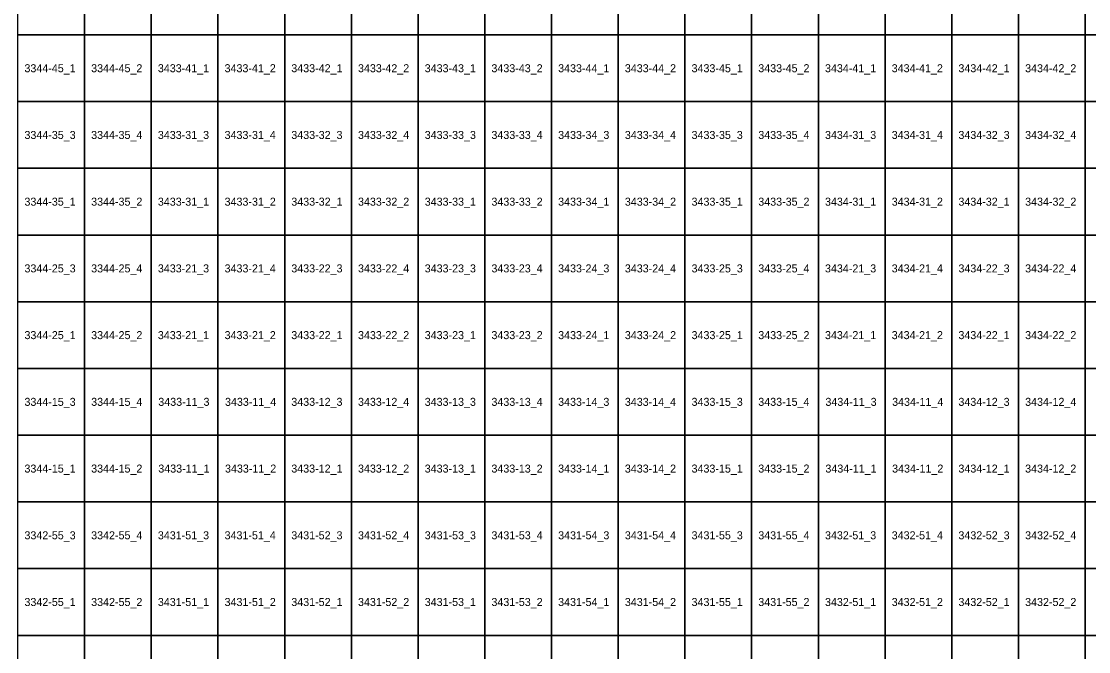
# Model space of a CAD drawing. Extents: x 312500 to 765000, y 172500 to 440000.
# Drawn here: x 595132 to 635129, y 269390 to 293007 of the extents above; entities that cross this region are included whole.
import ezdxf

# ---------------------------------------------------------------- set-up
doc = ezdxf.new("R2010")
doc.units = 0
doc.layers.add('Topo5_ramis_TKS2025', color=7, linetype='Continuous')
doc.layers.add('Topo5_ramis_TKS2025_Nr', color=7, linetype='Continuous')

msp = doc.modelspace()

# ---------------------------------------------------------------- linework, layer by layer
at = {"layer": 'Topo5_ramis_TKS2025'}
for points in [[(595000, 292500), (595000, 295000), (597500, 295000), (597500, 292500), (595000, 292500)], [(597500, 292500), (597500, 295000), (600000, 295000), (600000, 292500), (597500, 292500)], [(600000, 292500), (600000, 295000), (602500, 295000), (602500, 292500), (600000, 292500)], [(602500, 292500), (602500, 295000), (605000, 295000), (605000, 292500), (602500, 292500)], [(605000, 292500), (605000, 295000), (607500, 295000), (607500, 292500), (605000, 292500)], [(607500, 292500), (607500, 295000), (610000, 295000), (610000, 292500), (607500, 292500)], [(610000, 292500), (610000, 295000), (612500, 295000), (612500, 292500), (610000, 292500)], [(612500, 292500), (612500, 295000), (615000, 295000), (615000, 292500), (612500, 292500)], [(615000, 292500), (615000, 295000), (617500, 295000), (617500, 292500), (615000, 292500)], [(617500, 292500), (617500, 295000), (620000, 295000), (620000, 292500), (617500, 292500)], [(620000, 292500), (620000, 295000), (622500, 295000), (622500, 292500), (620000, 292500)], [(622500, 292500), (622500, 295000), (625000, 295000), (625000, 292500), (622500, 292500)], [(625000, 292500), (625000, 295000), (627500, 295000), (627500, 292500), (625000, 292500)], [(627500, 292500), (627500, 295000), (630000, 295000), (630000, 292500), (627500, 292500)], [(630000, 292500), (630000, 295000), (632500, 295000), (632500, 292500), (630000, 292500)], [(632500, 292500), (632500, 295000), (635000, 295000), (635000, 292500), (632500, 292500)], [(635000, 292500), (635000, 295000), (637500, 295000), (637500, 292500), (635000, 292500)], [(595000, 290000), (595000, 292500), (597500, 292500), (597500, 290000), (595000, 290000)], [(597500, 290000), (597500, 292500), (600000, 292500), (600000, 290000), (597500, 290000)], [(600000, 290000), (600000, 292500), (602500, 292500), (602500, 290000), (600000, 290000)], [(602500, 290000), (602500, 292500), (605000, 292500), (605000, 290000), (602500, 290000)], [(605000, 290000), (605000, 292500), (607500, 292500), (607500, 290000), (605000, 290000)], [(607500, 290000), (607500, 292500), (610000, 292500), (610000, 290000), (607500, 290000)], [(610000, 290000), (610000, 292500), (612500, 292500), (612500, 290000), (610000, 290000)], [(612500, 290000), (612500, 292500), (615000, 292500), (615000, 290000), (612500, 290000)], [(615000, 290000), (615000, 292500), (617500, 292500), (617500, 290000), (615000, 290000)], [(617500, 290000), (617500, 292500), (620000, 292500), (620000, 290000), (617500, 290000)], [(620000, 290000), (620000, 292500), (622500, 292500), (622500, 290000), (620000, 290000)], [(622500, 290000), (622500, 292500), (625000, 292500), (625000, 290000), (622500, 290000)], [(625000, 290000), (625000, 292500), (627500, 292500), (627500, 290000), (625000, 290000)], [(627500, 290000), (627500, 292500), (630000, 292500), (630000, 290000), (627500, 290000)], [(630000, 290000), (630000, 292500), (632500, 292500), (632500, 290000), (630000, 290000)], [(632500, 290000), (632500, 292500), (635000, 292500), (635000, 290000), (632500, 290000)], [(635000, 290000), (635000, 292500), (637500, 292500), (637500, 290000), (635000, 290000)], [(595000, 287500), (595000, 290000), (597500, 290000), (597500, 287500), (595000, 287500)], [(597500, 287500), (597500, 290000), (600000, 290000), (600000, 287500), (597500, 287500)], [(600000, 287500), (600000, 290000), (602500, 290000), (602500, 287500), (600000, 287500)], [(602500, 287500), (602500, 290000), (605000, 290000), (605000, 287500), (602500, 287500)], [(605000, 287500), (605000, 290000), (607500, 290000), (607500, 287500), (605000, 287500)], [(607500, 287500), (607500, 290000), (610000, 290000), (610000, 287500), (607500, 287500)], [(610000, 287500), (610000, 290000), (612500, 290000), (612500, 287500), (610000, 287500)], [(612500, 287500), (612500, 290000), (615000, 290000), (615000, 287500), (612500, 287500)], [(615000, 287500), (615000, 290000), (617500, 290000), (617500, 287500), (615000, 287500)], [(617500, 287500), (617500, 290000), (620000, 290000), (620000, 287500), (617500, 287500)], [(620000, 287500), (620000, 290000), (622500, 290000), (622500, 287500), (620000, 287500)], [(622500, 287500), (622500, 290000), (625000, 290000), (625000, 287500), (622500, 287500)], [(625000, 287500), (625000, 290000), (627500, 290000), (627500, 287500), (625000, 287500)], [(627500, 287500), (627500, 290000), (630000, 290000), (630000, 287500), (627500, 287500)], [(630000, 287500), (630000, 290000), (632500, 290000), (632500, 287500), (630000, 287500)], [(632500, 287500), (632500, 290000), (635000, 290000), (635000, 287500), (632500, 287500)], [(635000, 287500), (635000, 290000), (637500, 290000), (637500, 287500), (635000, 287500)], [(595000, 285000), (595000, 287500), (597500, 287500), (597500, 285000), (595000, 285000)], [(597500, 285000), (597500, 287500), (600000, 287500), (600000, 285000), (597500, 285000)], [(600000, 285000), (600000, 287500), (602500, 287500), (602500, 285000), (600000, 285000)], [(602500, 285000), (602500, 287500), (605000, 287500), (605000, 285000), (602500, 285000)], [(605000, 285000), (605000, 287500), (607500, 287500), (607500, 285000), (605000, 285000)], [(607500, 285000), (607500, 287500), (610000, 287500), (610000, 285000), (607500, 285000)], [(610000, 285000), (610000, 287500), (612500, 287500), (612500, 285000), (610000, 285000)], [(612500, 285000), (612500, 287500), (615000, 287500), (615000, 285000), (612500, 285000)], [(615000, 285000), (615000, 287500), (617500, 287500), (617500, 285000), (615000, 285000)], [(617500, 285000), (617500, 287500), (620000, 287500), (620000, 285000), (617500, 285000)], [(620000, 285000), (620000, 287500), (622500, 287500), (622500, 285000), (620000, 285000)], [(622500, 285000), (622500, 287500), (625000, 287500), (625000, 285000), (622500, 285000)], [(625000, 285000), (625000, 287500), (627500, 287500), (627500, 285000), (625000, 285000)], [(627500, 285000), (627500, 287500), (630000, 287500), (630000, 285000), (627500, 285000)], [(630000, 285000), (630000, 287500), (632500, 287500), (632500, 285000), (630000, 285000)], [(632500, 285000), (632500, 287500), (635000, 287500), (635000, 285000), (632500, 285000)], [(635000, 285000), (635000, 287500), (637500, 287500), (637500, 285000), (635000, 285000)], [(595000, 282500), (595000, 285000), (597500, 285000), (597500, 282500), (595000, 282500)], [(597500, 282500), (597500, 285000), (600000, 285000), (600000, 282500), (597500, 282500)], [(600000, 282500), (600000, 285000), (602500, 285000), (602500, 282500), (600000, 282500)], [(602500, 282500), (602500, 285000), (605000, 285000), (605000, 282500), (602500, 282500)], [(605000, 282500), (605000, 285000), (607500, 285000), (607500, 282500), (605000, 282500)], [(607500, 282500), (607500, 285000), (610000, 285000), (610000, 282500), (607500, 282500)], [(610000, 282500), (610000, 285000), (612500, 285000), (612500, 282500), (610000, 282500)], [(612500, 282500), (612500, 285000), (615000, 285000), (615000, 282500), (612500, 282500)], [(615000, 282500), (615000, 285000), (617500, 285000), (617500, 282500), (615000, 282500)], [(617500, 282500), (617500, 285000), (620000, 285000), (620000, 282500), (617500, 282500)], [(620000, 282500), (620000, 285000), (622500, 285000), (622500, 282500), (620000, 282500)], [(622500, 282500), (622500, 285000), (625000, 285000), (625000, 282500), (622500, 282500)], [(625000, 282500), (625000, 285000), (627500, 285000), (627500, 282500), (625000, 282500)], [(627500, 282500), (627500, 285000), (630000, 285000), (630000, 282500), (627500, 282500)], [(630000, 282500), (630000, 285000), (632500, 285000), (632500, 282500), (630000, 282500)], [(632500, 282500), (632500, 285000), (635000, 285000), (635000, 282500), (632500, 282500)], [(635000, 282500), (635000, 285000), (637500, 285000), (637500, 282500), (635000, 282500)], [(595000, 280000), (595000, 282500), (597500, 282500), (597500, 280000), (595000, 280000)], [(597500, 280000), (597500, 282500), (600000, 282500), (600000, 280000), (597500, 280000)], [(600000, 280000), (600000, 282500), (602500, 282500), (602500, 280000), (600000, 280000)], [(602500, 280000), (602500, 282500), (605000, 282500), (605000, 280000), (602500, 280000)], [(605000, 280000), (605000, 282500), (607500, 282500), (607500, 280000), (605000, 280000)], [(607500, 280000), (607500, 282500), (610000, 282500), (610000, 280000), (607500, 280000)], [(610000, 280000), (610000, 282500), (612500, 282500), (612500, 280000), (610000, 280000)], [(612500, 280000), (612500, 282500), (615000, 282500), (615000, 280000), (612500, 280000)], [(615000, 280000), (615000, 282500), (617500, 282500), (617500, 280000), (615000, 280000)], [(617500, 280000), (617500, 282500), (620000, 282500), (620000, 280000), (617500, 280000)], [(620000, 280000), (620000, 282500), (622500, 282500), (622500, 280000), (620000, 280000)], [(622500, 280000), (622500, 282500), (625000, 282500), (625000, 280000), (622500, 280000)], [(625000, 280000), (625000, 282500), (627500, 282500), (627500, 280000), (625000, 280000)], [(627500, 280000), (627500, 282500), (630000, 282500), (630000, 280000), (627500, 280000)], [(630000, 280000), (630000, 282500), (632500, 282500), (632500, 280000), (630000, 280000)], [(632500, 280000), (632500, 282500), (635000, 282500), (635000, 280000), (632500, 280000)], [(635000, 280000), (635000, 282500), (637500, 282500), (637500, 280000), (635000, 280000)], [(595000, 277500), (595000, 280000), (597500, 280000), (597500, 277500), (595000, 277500)], [(597500, 277500), (597500, 280000), (600000, 280000), (600000, 277500), (597500, 277500)], [(600000, 277500), (600000, 280000), (602500, 280000), (602500, 277500), (600000, 277500)], [(602500, 277500), (602500, 280000), (605000, 280000), (605000, 277500), (602500, 277500)], [(605000, 277500), (605000, 280000), (607500, 280000), (607500, 277500), (605000, 277500)], [(607500, 277500), (607500, 280000), (610000, 280000), (610000, 277500), (607500, 277500)], [(610000, 277500), (610000, 280000), (612500, 280000), (612500, 277500), (610000, 277500)], [(612500, 277500), (612500, 280000), (615000, 280000), (615000, 277500), (612500, 277500)], [(615000, 277500), (615000, 280000), (617500, 280000), (617500, 277500), (615000, 277500)], [(617500, 277500), (617500, 280000), (620000, 280000), (620000, 277500), (617500, 277500)], [(620000, 277500), (620000, 280000), (622500, 280000), (622500, 277500), (620000, 277500)], [(622500, 277500), (622500, 280000), (625000, 280000), (625000, 277500), (622500, 277500)], [(625000, 277500), (625000, 280000), (627500, 280000), (627500, 277500), (625000, 277500)], [(627500, 277500), (627500, 280000), (630000, 280000), (630000, 277500), (627500, 277500)], [(630000, 277500), (630000, 280000), (632500, 280000), (632500, 277500), (630000, 277500)], [(632500, 277500), (632500, 280000), (635000, 280000), (635000, 277500), (632500, 277500)], [(635000, 277500), (635000, 280000), (637500, 280000), (637500, 277500), (635000, 277500)], [(595000, 275000), (595000, 277500), (597500, 277500), (597500, 275000), (595000, 275000)], [(597500, 275000), (597500, 277500), (600000, 277500), (600000, 275000), (597500, 275000)], [(600000, 275000), (600000, 277500), (602500, 277500), (602500, 275000), (600000, 275000)], [(602500, 275000), (602500, 277500), (605000, 277500), (605000, 275000), (602500, 275000)], [(605000, 275000), (605000, 277500), (607500, 277500), (607500, 275000), (605000, 275000)], [(607500, 275000), (607500, 277500), (610000, 277500), (610000, 275000), (607500, 275000)], [(610000, 275000), (610000, 277500), (612500, 277500), (612500, 275000), (610000, 275000)], [(612500, 275000), (612500, 277500), (615000, 277500), (615000, 275000), (612500, 275000)], [(615000, 275000), (615000, 277500), (617500, 277500), (617500, 275000), (615000, 275000)], [(617500, 275000), (617500, 277500), (620000, 277500), (620000, 275000), (617500, 275000)], [(620000, 275000), (620000, 277500), (622500, 277500), (622500, 275000), (620000, 275000)], [(622500, 275000), (622500, 277500), (625000, 277500), (625000, 275000), (622500, 275000)], [(625000, 275000), (625000, 277500), (627500, 277500), (627500, 275000), (625000, 275000)], [(627500, 275000), (627500, 277500), (630000, 277500), (630000, 275000), (627500, 275000)], [(630000, 275000), (630000, 277500), (632500, 277500), (632500, 275000), (630000, 275000)], [(632500, 275000), (632500, 277500), (635000, 277500), (635000, 275000), (632500, 275000)], [(635000, 275000), (635000, 277500), (637500, 277500), (637500, 275000), (635000, 275000)], [(595000, 272500), (595000, 275000), (597500, 275000), (597500, 272500), (595000, 272500)], [(597500, 272500), (597500, 275000), (600000, 275000), (600000, 272500), (597500, 272500)], [(600000, 272500), (600000, 275000), (602500, 275000), (602500, 272500), (600000, 272500)], [(602500, 272500), (602500, 275000), (605000, 275000), (605000, 272500), (602500, 272500)], [(605000, 272500), (605000, 275000), (607500, 275000), (607500, 272500), (605000, 272500)], [(607500, 272500), (607500, 275000), (610000, 275000), (610000, 272500), (607500, 272500)], [(610000, 272500), (610000, 275000), (612500, 275000), (612500, 272500), (610000, 272500)], [(612500, 272500), (612500, 275000), (615000, 275000), (615000, 272500), (612500, 272500)], [(615000, 272500), (615000, 275000), (617500, 275000), (617500, 272500), (615000, 272500)], [(617500, 272500), (617500, 275000), (620000, 275000), (620000, 272500), (617500, 272500)], [(620000, 272500), (620000, 275000), (622500, 275000), (622500, 272500), (620000, 272500)], [(622500, 272500), (622500, 275000), (625000, 275000), (625000, 272500), (622500, 272500)], [(625000, 272500), (625000, 275000), (627500, 275000), (627500, 272500), (625000, 272500)], [(627500, 272500), (627500, 275000), (630000, 275000), (630000, 272500), (627500, 272500)], [(630000, 272500), (630000, 275000), (632500, 275000), (632500, 272500), (630000, 272500)], [(632500, 272500), (632500, 275000), (635000, 275000), (635000, 272500), (632500, 272500)], [(635000, 272500), (635000, 275000), (637500, 275000), (637500, 272500), (635000, 272500)], [(595000, 270000), (595000, 272500), (597500, 272500), (597500, 270000), (595000, 270000)], [(597500, 270000), (597500, 272500), (600000, 272500), (600000, 270000), (597500, 270000)], [(600000, 270000), (600000, 272500), (602500, 272500), (602500, 270000), (600000, 270000)], [(602500, 270000), (602500, 272500), (605000, 272500), (605000, 270000), (602500, 270000)], [(605000, 270000), (605000, 272500), (607500, 272500), (607500, 270000), (605000, 270000)], [(607500, 270000), (607500, 272500), (610000, 272500), (610000, 270000), (607500, 270000)], [(610000, 270000), (610000, 272500), (612500, 272500), (612500, 270000), (610000, 270000)], [(612500, 270000), (612500, 272500), (615000, 272500), (615000, 270000), (612500, 270000)], [(615000, 270000), (615000, 272500), (617500, 272500), (617500, 270000), (615000, 270000)], [(617500, 270000), (617500, 272500), (620000, 272500), (620000, 270000), (617500, 270000)], [(620000, 270000), (620000, 272500), (622500, 272500), (622500, 270000), (620000, 270000)], [(622500, 270000), (622500, 272500), (625000, 272500), (625000, 270000), (622500, 270000)], [(625000, 270000), (625000, 272500), (627500, 272500), (627500, 270000), (625000, 270000)], [(627500, 270000), (627500, 272500), (630000, 272500), (630000, 270000), (627500, 270000)], [(630000, 270000), (630000, 272500), (632500, 272500), (632500, 270000), (630000, 270000)], [(632500, 270000), (632500, 272500), (635000, 272500), (635000, 270000), (632500, 270000)], [(635000, 270000), (635000, 272500), (637500, 272500), (637500, 270000), (635000, 270000)], [(595000, 267500), (595000, 270000), (597500, 270000), (597500, 267500), (595000, 267500)], [(597500, 267500), (597500, 270000), (600000, 270000), (600000, 267500), (597500, 267500)], [(600000, 267500), (600000, 270000), (602500, 270000), (602500, 267500), (600000, 267500)], [(602500, 267500), (602500, 270000), (605000, 270000), (605000, 267500), (602500, 267500)], [(605000, 267500), (605000, 270000), (607500, 270000), (607500, 267500), (605000, 267500)], [(607500, 267500), (607500, 270000), (610000, 270000), (610000, 267500), (607500, 267500)], [(610000, 267500), (610000, 270000), (612500, 270000), (612500, 267500), (610000, 267500)], [(612500, 267500), (612500, 270000), (615000, 270000), (615000, 267500), (612500, 267500)], [(615000, 267500), (615000, 270000), (617500, 270000), (617500, 267500), (615000, 267500)], [(617500, 267500), (617500, 270000), (620000, 270000), (620000, 267500), (617500, 267500)], [(620000, 267500), (620000, 270000), (622500, 270000), (622500, 267500), (620000, 267500)], [(622500, 267500), (622500, 270000), (625000, 270000), (625000, 267500), (622500, 267500)], [(625000, 267500), (625000, 270000), (627500, 270000), (627500, 267500), (625000, 267500)], [(627500, 267500), (627500, 270000), (630000, 270000), (630000, 267500), (627500, 267500)], [(630000, 267500), (630000, 270000), (632500, 270000), (632500, 267500), (630000, 267500)], [(632500, 267500), (632500, 270000), (635000, 270000), (635000, 267500), (632500, 267500)], [(635000, 267500), (635000, 270000), (637500, 270000), (637500, 267500), (635000, 267500)]]:
    msp.add_lwpolyline(points, dxfattribs=at)

# ---------------------------------------------------------------- texts
at = {"layer": 'Topo5_ramis_TKS2025_Nr'}
for s, p in [('3344-45_1', (595248, 291100)), ('3344-45_2', (597748, 291100)), ('3433-41_1', (600248, 291100)), ('3433-41_2', (602748, 291100)), ('3433-42_1', (605248, 291100)), ('3433-42_2', (607748, 291100)), ('3433-43_1', (610248, 291100)), ('3433-43_2', (612748, 291100)), ('3433-44_1', (615248, 291100)), ('3433-44_2', (617748, 291100)), ('3433-45_1', (620248, 291100)), ('3433-45_2', (622748, 291100)), ('3434-41_1', (625248, 291100)), ('3434-41_2', (627748, 291100)), ('3434-42_1', (630248, 291100)), ('3434-42_2', (632748, 291100)), ('3344-35_3', (595248, 288600)), ('3344-35_4', (597748, 288600)), ('3433-31_3', (600248, 288600)), ('3433-31_4', (602748, 288600)), ('3433-32_3', (605248, 288600)), ('3433-32_4', (607748, 288600)), ('3433-33_3', (610248, 288600)), ('3433-33_4', (612748, 288600)), ('3433-34_3', (615248, 288600)), ('3433-34_4', (617748, 288600)), ('3433-35_3', (620248, 288600)), ('3433-35_4', (622748, 288600)), ('3434-31_3', (625248, 288600)), ('3434-31_4', (627748, 288600)), ('3434-32_3', (630248, 288600)), ('3434-32_4', (632748, 288600)), ('3344-35_1', (595248, 286100)), ('3344-35_2', (597748, 286100)), ('3433-31_1', (600248, 286100)), ('3433-31_2', (602748, 286100)), ('3433-32_1', (605248, 286100)), ('3433-32_2', (607748, 286100)), ('3433-33_1', (610248, 286100)), ('3433-33_2', (612748, 286100)), ('3433-34_1', (615248, 286100)), ('3433-34_2', (617748, 286100)), ('3433-35_1', (620248, 286100)), ('3433-35_2', (622748, 286100)), ('3434-31_1', (625248, 286100)), ('3434-31_2', (627748, 286100)), ('3434-32_1', (630248, 286100)), ('3434-32_2', (632748, 286100)), ('3344-25_3', (595248, 283600)), ('3344-25_4', (597748, 283600)), ('3433-21_3', (600248, 283600)), ('3433-21_4', (602748, 283600)), ('3433-22_3', (605248, 283600)), ('3433-22_4', (607748, 283600)), ('3433-23_3', (610248, 283600)), ('3433-23_4', (612748, 283600)), ('3433-24_3', (615248, 283600)), ('3433-24_4', (617748, 283600)), ('3433-25_3', (620248, 283600)), ('3433-25_4', (622748, 283600)), ('3434-21_3', (625248, 283600)), ('3434-21_4', (627748, 283600)), ('3434-22_3', (630248, 283600)), ('3434-22_4', (632748, 283600)), ('3344-25_1', (595248, 281100)), ('3344-25_2', (597748, 281100)), ('3433-21_1', (600248, 281100)), ('3433-21_2', (602748, 281100)), ('3433-22_1', (605248, 281100)), ('3433-22_2', (607748, 281100)), ('3433-23_1', (610248, 281100)), ('3433-23_2', (612748, 281100)), ('3433-24_1', (615248, 281100)), ('3433-24_2', (617748, 281100)), ('3433-25_1', (620248, 281100)), ('3433-25_2', (622748, 281100)), ('3434-21_1', (625248, 281100)), ('3434-21_2', (627748, 281100)), ('3434-22_1', (630248, 281100)), ('3434-22_2', (632748, 281100)), ('3344-15_3', (595248, 278600)), ('3344-15_4', (597748, 278600)), ('3433-11_3', (600264, 278600)), ('3433-11_4', (602764, 278600)), ('3433-12_3', (605248, 278600)), ('3433-12_4', (607748, 278600)), ('3433-13_3', (610248, 278600)), ('3433-13_4', (612748, 278600)), ('3433-14_3', (615248, 278600)), ('3433-14_4', (617748, 278600)), ('3433-15_3', (620248, 278600)), ('3433-15_4', (622748, 278600)), ('3434-11_3', (625264, 278600)), ('3434-11_4', (627764, 278600)), ('3434-12_3', (630248, 278600)), ('3434-12_4', (632748, 278600)), ('3344-15_1', (595248, 276100)), ('3344-15_2', (597748, 276100)), ('3433-11_1', (600264, 276100)), ('3433-11_2', (602764, 276100)), ('3433-12_1', (605248, 276100)), ('3433-12_2', (607748, 276100)), ('3433-13_1', (610248, 276100)), ('3433-13_2', (612748, 276100)), ('3433-14_1', (615248, 276100)), ('3433-14_2', (617748, 276100)), ('3433-15_1', (620248, 276100)), ('3433-15_2', (622748, 276100)), ('3434-11_1', (625264, 276100)), ('3434-11_2', (627764, 276100)), ('3434-12_1', (630248, 276100)), ('3434-12_2', (632748, 276100)), ('3342-55_3', (595248, 273600)), ('3342-55_4', (597748, 273600)), ('3431-51_3', (600248, 273600)), ('3431-51_4', (602748, 273600)), ('3431-52_3', (605248, 273600)), ('3431-52_4', (607748, 273600)), ('3431-53_3', (610248, 273600)), ('3431-53_4', (612748, 273600)), ('3431-54_3', (615248, 273600)), ('3431-54_4', (617748, 273600)), ('3431-55_3', (620248, 273600)), ('3431-55_4', (622748, 273600)), ('3432-51_3', (625248, 273600)), ('3432-51_4', (627748, 273600)), ('3432-52_3', (630248, 273600)), ('3432-52_4', (632748, 273600)), ('3342-55_1', (595248, 271100)), ('3342-55_2', (597748, 271100)), ('3431-51_1', (600248, 271100)), ('3431-51_2', (602748, 271100)), ('3431-52_1', (605248, 271100)), ('3431-52_2', (607748, 271100)), ('3431-53_1', (610248, 271100)), ('3431-53_2', (612748, 271100)), ('3431-54_1', (615248, 271100)), ('3431-54_2', (617748, 271100)), ('3431-55_1', (620248, 271100)), ('3431-55_2', (622748, 271100)), ('3432-51_1', (625248, 271100)), ('3432-51_2', (627748, 271100)), ('3432-52_1', (630248, 271100)), ('3432-52_2', (632748, 271100))]:
    msp.add_text(s, height=300, dxfattribs=at).set_placement(p)

doc.saveas('drawing.dxf')
